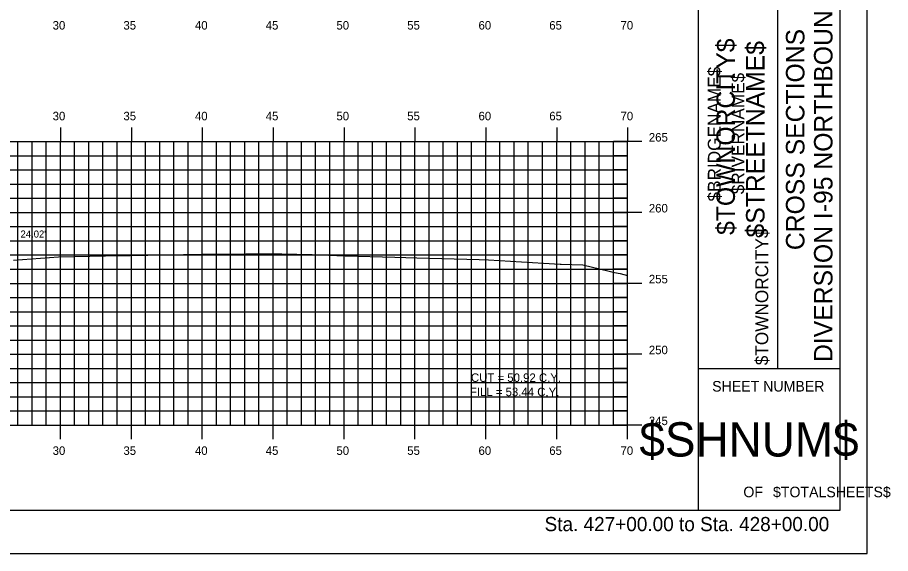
# Model space of a CAD drawing. Extents: x 1160718 to 1173142, y 616002 to 617630.
# Drawn here: x 1170876.4 to 1170938, y 616613.9 to 616651.7 of the extents above; entities that cross this region are included whole.
import ezdxf

# ---------------------------------------------------------------- set-up
doc = ezdxf.new("R2010")
doc.units = 0
for name, color, linetype in [('ANNOTATION', 7, 'Continuous'), ('BORDER', 7, 'Continuous'), ('BRIDGE_TITLE', 7, 'Continuous'), ('H_V ANNOTATION', 7, 'Continuous'), ('HIGHWAY_TITLE', 7, 'Continuous'), ('MAJOR', 7, 'Continuous'), ('MINOR', 7, 'Continuous'), ('PLOT BOUNDARY', 7, 'Continuous'), ('S_Roadway_Centerline', 7, 'Continuous')]:
    doc.layers.add(name, color=color, linetype=linetype)

msp = doc.modelspace()

# ---------------------------------------------------------------- linework, layer by layer
at = {"layer": 'BORDER'}
for p, q in [((1170924.42, 616616.931), (1170924.42, 616721.931)), ((1170934.42, 616616.931), (1170934.42, 616721.931)), ((1170930.011, 616626.931), (1170930.011, 616661.931)), ((1170924.42, 616626.931), (1170934.42, 616626.931)), ((1170774.42, 616616.928), (1170934.42, 616616.928))]:
    msp.add_line(p, q, dxfattribs=at)
at = {"layer": 'MAJOR'}
for p, q in [((1170879.42, 616643.93), (1170879.42, 616642.928)), ((1170884.42, 616643.93), (1170884.42, 616642.928)), ((1170889.42, 616643.93), (1170889.42, 616642.928)), ((1170894.42, 616643.93), (1170894.42, 616642.928)), ((1170899.42, 616643.93), (1170899.42, 616642.928)), ((1170904.42, 616643.93), (1170904.42, 616642.928)), ((1170909.42, 616643.93), (1170909.42, 616642.928)), ((1170914.42, 616643.93), (1170914.42, 616642.928)), ((1170919.42, 616643.93), (1170919.42, 616642.928)), ((1170779.42, 616642.928), (1170919.42, 616642.928)), ((1170779.42, 616642.928), (1170919.42, 616642.928)), ((1170879.42, 616622.928), (1170879.42, 616642.928)), ((1170884.42, 616622.928), (1170884.42, 616642.928)), ((1170889.42, 616622.928), (1170889.42, 616642.928)), ((1170894.42, 616622.928), (1170894.42, 616642.928)), ((1170899.42, 616622.928), (1170899.42, 616642.928)), ((1170904.42, 616622.928), (1170904.42, 616642.928)), ((1170909.42, 616622.928), (1170909.42, 616642.928)), ((1170914.42, 616622.928), (1170914.42, 616642.928)), ((1170920.422, 616642.928), (1170918.418, 616642.928)), ((1170919.42, 616622.928), (1170919.42, 616642.928)), ((1170919.42, 616622.928), (1170919.42, 616642.928)), ((1170779.42, 616637.928), (1170919.42, 616637.928)), ((1170920.422, 616637.928), (1170918.418, 616637.928)), ((1170779.42, 616632.928), (1170919.42, 616632.928)), ((1170920.422, 616632.928), (1170918.418, 616632.928)), ((1170823.863, 616630.928), (1170919.42, 616630.928)), ((1170779.42, 616627.928), (1170919.42, 616627.928)), ((1170920.422, 616627.928), (1170918.418, 616627.928)), ((1170779.42, 616622.928), (1170919.42, 616622.928)), ((1170779.42, 616622.928), (1170919.42, 616622.928)), ((1170879.42, 616621.926), (1170879.42, 616622.928)), ((1170884.42, 616621.926), (1170884.42, 616622.928)), ((1170889.42, 616621.926), (1170889.42, 616622.928)), ((1170894.42, 616621.926), (1170894.42, 616622.928)), ((1170899.42, 616621.926), (1170899.42, 616622.928)), ((1170904.42, 616621.926), (1170904.42, 616622.928)), ((1170909.42, 616621.926), (1170909.42, 616622.928)), ((1170914.42, 616621.926), (1170914.42, 616622.928)), ((1170920.422, 616622.928), (1170918.418, 616622.928)), ((1170919.42, 616621.926), (1170919.42, 616622.928))]:
    msp.add_line(p, q, dxfattribs=at)
at = {"layer": 'MINOR'}
for p, q in [((1170876.42, 616622.928), (1170876.42, 616642.928)), ((1170877.42, 616622.928), (1170877.42, 616642.928)), ((1170878.42, 616622.928), (1170878.42, 616642.928)), ((1170880.42, 616622.928), (1170880.42, 616642.928)), ((1170881.42, 616622.928), (1170881.42, 616642.928)), ((1170882.42, 616622.928), (1170882.42, 616642.928)), ((1170883.42, 616622.928), (1170883.42, 616642.928)), ((1170885.42, 616622.928), (1170885.42, 616642.928)), ((1170886.42, 616622.928), (1170886.42, 616642.928)), ((1170887.42, 616622.928), (1170887.42, 616642.928)), ((1170888.42, 616622.928), (1170888.42, 616642.928)), ((1170890.42, 616622.928), (1170890.42, 616642.928)), ((1170891.42, 616622.928), (1170891.42, 616642.928)), ((1170892.42, 616622.928), (1170892.42, 616642.928)), ((1170893.42, 616622.928), (1170893.42, 616642.928)), ((1170895.42, 616622.928), (1170895.42, 616642.928)), ((1170896.42, 616622.928), (1170896.42, 616642.928)), ((1170897.42, 616622.928), (1170897.42, 616642.928)), ((1170898.42, 616622.928), (1170898.42, 616642.928)), ((1170900.42, 616622.928), (1170900.42, 616642.928)), ((1170901.42, 616622.928), (1170901.42, 616642.928)), ((1170902.42, 616622.928), (1170902.42, 616642.928)), ((1170903.42, 616622.928), (1170903.42, 616642.928)), ((1170905.42, 616622.928), (1170905.42, 616642.928)), ((1170906.42, 616622.928), (1170906.42, 616642.928)), ((1170907.42, 616622.928), (1170907.42, 616642.928)), ((1170908.42, 616622.928), (1170908.42, 616642.928)), ((1170910.42, 616622.928), (1170910.42, 616642.928)), ((1170911.42, 616622.928), (1170911.42, 616642.928)), ((1170912.42, 616622.928), (1170912.42, 616642.928)), ((1170913.42, 616622.928), (1170913.42, 616642.928)), ((1170915.42, 616622.928), (1170915.42, 616642.928)), ((1170916.42, 616622.928), (1170916.42, 616642.928)), ((1170917.42, 616622.928), (1170917.42, 616642.928)), ((1170918.42, 616622.928), (1170918.42, 616642.928)), ((1170779.42, 616641.928), (1170919.42, 616641.928)), ((1170919.42, 616641.928), (1170918.418, 616641.928)), ((1170779.42, 616640.928), (1170919.42, 616640.928)), ((1170919.42, 616640.928), (1170918.418, 616640.928)), ((1170779.42, 616639.928), (1170919.42, 616639.928)), ((1170919.42, 616639.928), (1170918.418, 616639.928)), ((1170779.42, 616638.928), (1170919.42, 616638.928)), ((1170919.42, 616638.928), (1170918.418, 616638.928)), ((1170779.42, 616636.928), (1170919.42, 616636.928)), ((1170919.42, 616636.928), (1170918.418, 616636.928)), ((1170779.42, 616635.928), (1170919.42, 616635.928)), ((1170919.42, 616635.928), (1170918.418, 616635.928)), ((1170779.42, 616634.928), (1170919.42, 616634.928)), ((1170919.42, 616634.928), (1170918.418, 616634.928)), ((1170779.42, 616633.928), (1170919.42, 616633.928)), ((1170919.42, 616633.928), (1170918.418, 616633.928)), ((1170779.42, 616631.928), (1170919.42, 616631.928)), ((1170919.42, 616631.928), (1170918.418, 616631.928)), ((1170779.42, 616630.928), (1170919.42, 616630.928)), ((1170919.42, 616630.928), (1170918.418, 616630.928)), ((1170779.42, 616629.928), (1170919.42, 616629.928)), ((1170919.42, 616629.928), (1170918.418, 616629.928)), ((1170779.42, 616628.928), (1170919.42, 616628.928)), ((1170919.42, 616628.928), (1170918.418, 616628.928)), ((1170779.42, 616626.928), (1170919.42, 616626.928)), ((1170919.42, 616626.928), (1170918.418, 616626.928)), ((1170779.42, 616625.928), (1170919.42, 616625.928)), ((1170919.42, 616625.928), (1170918.418, 616625.928)), ((1170779.42, 616624.928), (1170919.42, 616624.928)), ((1170919.42, 616624.928), (1170918.418, 616624.928)), ((1170779.42, 616623.928), (1170919.42, 616623.928)), ((1170919.42, 616623.928), (1170918.418, 616623.928))]:
    msp.add_line(p, q, dxfattribs=at)
at = {"layer": 'PLOT BOUNDARY'}
msp.add_lwpolyline([(1170766.327, 616613.869), (1170936.327, 616613.869), (1170936.327, 616723.869), (1170766.327, 616723.869)], close=True, dxfattribs=at)
at = {"layer": 'S_Roadway_Centerline'}
msp.add_lwpolyline([(1170876.116, 616634.569), (1170879.288, 616634.791), (1170879.29, 616634.791), (1170883.693, 616634.884), (1170884.344, 616634.899), (1170888.098, 616634.957), (1170889.398, 616634.976), (1170892.502, 616635.001), (1170894.453, 616635.017), (1170894.756, 616635.018), (1170895.024, 616635.016), (1170897.175, 616634.951), (1170899.507, 616634.879), (1170903.011, 616634.77), (1170904.561, 616634.723), (1170908.942, 616634.599), (1170909.615, 616634.579), (1170913.481, 616634.353), (1170914.669, 616634.284), (1170914.738, 616634.282), (1170916.267, 616634.24), (1170918.127, 616633.796), (1170918.509, 616633.703), (1170918.891, 616633.625), (1170919.42, 616633.484)], dxfattribs=at)

# ---------------------------------------------------------------- texts
at = {"layer": 'ANNOTATION'}
msp.add_text("24.02'", height=0.5, dxfattribs=at).set_placement((1170876.603, 616636.155))
for s, p in [('CUT = 50.92 C.Y.', (1170908.373, 616625.978)), ('FILL = 53.44 C.Y.', (1170908.297, 616624.976))]:
    msp.add_text(s, height=0.6, rotation=359.92408, dxfattribs=at).set_placement(p)
at = {"layer": 'BORDER'}
for s, height, rotation, p in [('DIVERSION I-95 NORTHBOUND  ', 1.30428, 90, (1170933.874, 616627.379)), ('CROSS SECTIONS', 1.30428, 90, (1170931.896, 616635.27)), ('SHEET NUMBER', 0.74527, 360, (1170925.386, 616625.295)), ('$SHNUM$', 2.4194, 360, (1170920.254, 616620.711)), ('OF', 0.7453, 360, (1170927.587, 616617.841)), ('$TOTALSHEETS$', 0.74527, 360, (1170929.677, 616617.841))]:
    msp.add_text(s, height=height, rotation=rotation, dxfattribs=at).set_placement(p)
at = {"layer": 'BRIDGE_TITLE'}
for s, p in [('$BRIDGENAME$', (1170925.987, 616638.7)), ('$RIVERNAME$', (1170927.664, 616639.214)), ('$TOWNORCITY$', (1170929.341, 616627.152))]:
    msp.add_text(s, height=0.90716, rotation=90, dxfattribs=at).set_placement(p)
at = {"layer": 'H_V ANNOTATION'}
for s, height, p in [('30', 0.6, (1170878.869, 616650.828)), ('35', 0.6, (1170883.861, 616650.828)), ('40', 0.6, (1170888.906, 616650.828)), ('45', 0.6, (1170893.898, 616650.828)), ('50', 0.6, (1170898.885, 616650.828)), ('55', 0.6, (1170903.877, 616650.828)), ('60', 0.6, (1170908.906, 616650.828)), ('65', 0.6, (1170913.898, 616650.828)), ('70', 0.6, (1170918.922, 616650.828)), ('30', 0.6, (1170878.869, 616644.428)), ('35', 0.6, (1170883.861, 616644.428)), ('40', 0.6, (1170888.906, 616644.428)), ('45', 0.6, (1170893.898, 616644.428)), ('50', 0.6, (1170898.885, 616644.428)), ('55', 0.6, (1170903.877, 616644.428)), ('60', 0.6, (1170908.906, 616644.428)), ('65', 0.6, (1170913.898, 616644.428)), ('70', 0.6, (1170918.922, 616644.428)), ('265', 0.6, (1170920.92, 616642.928)), ('260', 0.6, (1170920.92, 616637.928)), ('255', 0.6, (1170920.92, 616632.928)), ('250', 0.6, (1170920.92, 616627.928)), ('245', 0.6, (1170920.92, 616622.928)), ('30', 0.6, (1170878.869, 616620.828)), ('35', 0.6, (1170883.861, 616620.828)), ('40', 0.6, (1170888.906, 616620.828)), ('45', 0.6, (1170893.898, 616620.828)), ('50', 0.6, (1170898.885, 616620.828)), ('55', 0.6, (1170903.877, 616620.828)), ('60', 0.6, (1170908.906, 616620.828)), ('65', 0.6, (1170913.898, 616620.828)), ('70', 0.6, (1170918.922, 616620.828)), ('Sta. 427+00.00 to Sta. 428+00.00', 1.0002, (1170913.566, 616615.448))]:
    msp.add_text(s, height=height, dxfattribs=at).set_placement(p)
at = {"layer": 'HIGHWAY_TITLE'}
for s, p in [('$TOWNORCITY$', (1170926.993, 616636.34)), ('$STREETNAME$', (1170929.08, 616636.16))]:
    msp.add_text(s, height=1.30428, rotation=90, dxfattribs=at).set_placement(p)

doc.saveas('drawing.dxf')
